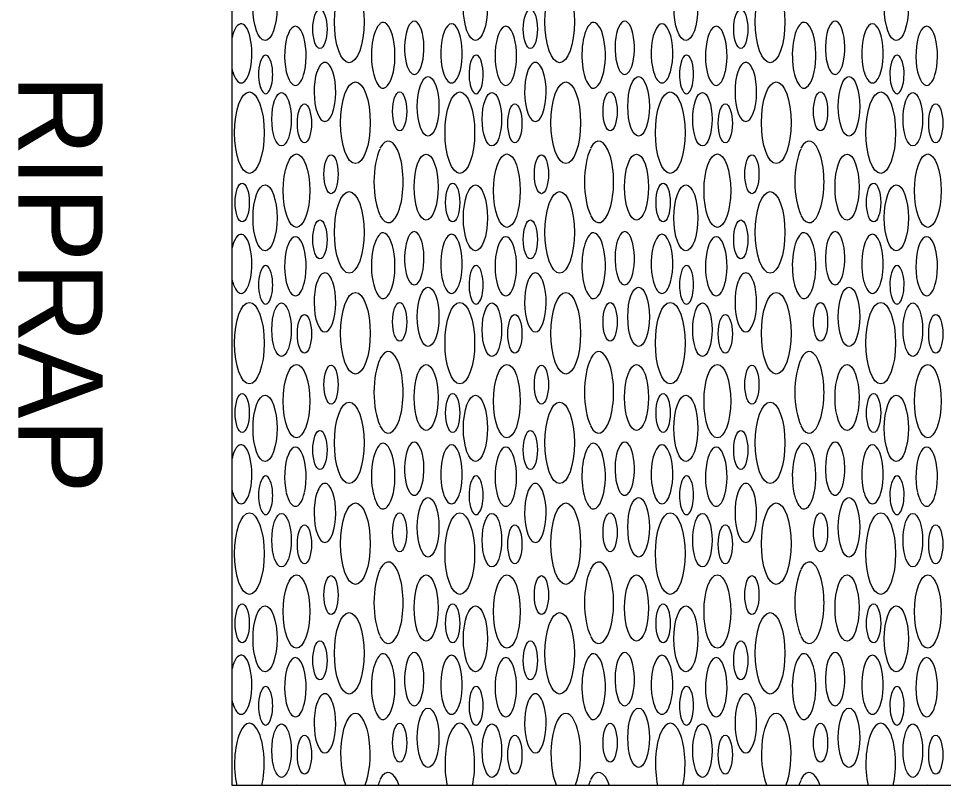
# Model space of a CAD drawing. Extents: x 2751 to 3858, y 6160 to 8366.
# Drawn here: x 3314.5 to 3534.1, y 6603.9 to 6786.1 of the extents above; entities that cross this region are included whole.
import ezdxf

# ---------------------------------------------------------------- set-up
doc = ezdxf.new("R2010")
doc.units = 0
doc.layers.add('Default', color=7, linetype='Continuous')

msp = doc.modelspace()

# ---------------------------------------------------------------- linework, layer by layer
at = {"layer": 'Default'}
msp.add_lwpolyline([(3658.73, 6840.75), (3658.73, 6603.91), (3365.15, 6603.91), (3365.15, 6840.75)], close=True, dxfattribs=at)
for centre, major_axis in [((3372.98, 6788.77), (0, 7.85)), ((3422.94, 6788.77), (0, 7.85)), ((3472.91, 6788.77), (0, 7.85)), ((3522.88, 6788.77), (0, 7.85)), ((3392.97, 6785.32), (0, 9.69)), ((3442.94, 6785.32), (0, 9.69)), ((3492.91, 6785.32), (0, 9.69)), ((3386.02, 6783.64), (0, 4.63)), ((3435.98, 6783.64), (0, 4.63)), ((3485.95, 6783.64), (0, 4.63)), ((3411.71, 6765.26), (0, 7.06)), ((3461.68, 6765.26), (0, 7.06)), ((3511.64, 6765.26), (0, 7.06)), ((3394.44, 6761.36), (0, 9.69)), ((3444.4, 6761.36), (0, 9.69)), ((3494.37, 6761.36), (0, 9.69)), ((3369.27, 6759.01), (0, 9.69)), ((3376.9, 6762.2), (0, 6.35)), ((3404.95, 6764.07), (0, 4.63)), ((3419.24, 6759.01), (0, 9.69)), ((3426.86, 6762.2), (0, 6.35)), ((3454.92, 6764.07), (0, 4.63)), ((3469.2, 6759.01), (0, 9.69)), ((3476.83, 6762.2), (0, 6.35)), ((3504.89, 6764.07), (0, 4.63)), ((3519.17, 6759.01), (0, 9.69)), ((3526.8, 6762.2), (0, 6.35)), ((3382.34, 6761.22), (0, 4.63)), ((3432.31, 6761.22), (0, 4.63)), ((3482.27, 6761.22), (0, 4.63)), ((3532.24, 6761.22), (0, 4.63)), ((3380.45, 6745.24), (0, 8.72)), ((3388.66, 6749.15), (0, 4.63)), ((3411.23, 6746.09), (0, 7.85)), ((3430.42, 6745.24), (0, 8.72)), ((3438.62, 6749.15), (0, 4.63)), ((3461.2, 6746.09), (0, 7.85)), ((3480.38, 6745.24), (0, 8.72)), ((3488.59, 6749.15), (0, 4.63)), ((3511.17, 6746.09), (0, 7.85)), ((3530.35, 6745.24), (0, 8.72)), ((3367.57, 6742.42), (0, 4.63)), ((3417.54, 6742.42), (0, 4.63)), ((3467.51, 6742.42), (0, 4.63)), ((3517.48, 6742.42), (0, 4.63)), ((3372.98, 6738.77), (0, 7.85)), ((3392.97, 6735.32), (0, 9.69)), ((3422.94, 6738.77), (0, 7.85)), ((3442.94, 6735.32), (0, 9.69)), ((3472.91, 6738.77), (0, 7.85)), ((3492.91, 6735.32), (0, 9.69)), ((3522.88, 6738.77), (0, 7.85)), ((3386.02, 6733.64), (0, 4.63)), ((3435.98, 6733.64), (0, 4.63)), ((3485.95, 6733.64), (0, 4.63)), ((3394.44, 6711.36), (0, 9.69)), ((3411.71, 6715.26), (0, 7.06)), ((3444.4, 6711.36), (0, 9.69)), ((3461.68, 6715.26), (0, 7.06)), ((3494.37, 6711.36), (0, 9.69)), ((3511.64, 6715.26), (0, 7.06)), ((3369.27, 6709.01), (0, 9.69)), ((3376.9, 6712.2), (0, 6.35)), ((3404.95, 6714.07), (0, 4.63)), ((3419.24, 6709.01), (0, 9.69)), ((3426.86, 6712.2), (0, 6.35)), ((3454.92, 6714.07), (0, 4.63)), ((3469.2, 6709.01), (0, 9.69)), ((3476.83, 6712.2), (0, 6.35)), ((3504.89, 6714.07), (0, 4.63)), ((3519.17, 6709.01), (0, 9.69)), ((3526.8, 6712.2), (0, 6.35)), ((3382.34, 6711.22), (0, 4.63)), ((3432.31, 6711.22), (0, 4.63)), ((3482.27, 6711.22), (0, 4.63)), ((3532.24, 6711.22), (0, 4.63)), ((3380.45, 6695.24), (0, 8.72)), ((3388.66, 6699.15), (0, 4.63)), ((3411.23, 6696.09), (0, 7.85)), ((3430.42, 6695.24), (0, 8.72)), ((3438.62, 6699.15), (0, 4.63)), ((3461.2, 6696.09), (0, 7.85)), ((3480.38, 6695.24), (0, 8.72)), ((3488.59, 6699.15), (0, 4.63)), ((3511.17, 6696.09), (0, 7.85)), ((3530.35, 6695.24), (0, 8.72)), ((3367.57, 6692.42), (0, 4.63)), ((3372.98, 6688.77), (0, 7.85)), ((3417.54, 6692.42), (0, 4.63)), ((3422.94, 6688.77), (0, 7.85)), ((3467.51, 6692.42), (0, 4.63)), ((3472.91, 6688.77), (0, 7.85)), ((3517.48, 6692.42), (0, 4.63)), ((3522.88, 6688.77), (0, 7.85)), ((3392.97, 6685.32), (0, 9.69)), ((3442.94, 6685.32), (0, 9.69)), ((3492.91, 6685.32), (0, 9.69)), ((3386.02, 6683.64), (0, 4.63)), ((3435.98, 6683.64), (0, 4.63)), ((3485.95, 6683.64), (0, 4.63)), ((3394.44, 6661.36), (0, 9.69)), ((3411.71, 6665.26), (0, 7.06)), ((3444.4, 6661.36), (0, 9.69)), ((3461.68, 6665.26), (0, 7.06)), ((3494.37, 6661.36), (0, 9.69)), ((3511.64, 6665.26), (0, 7.06)), ((3369.27, 6659.01), (0, 9.69)), ((3376.9, 6662.2), (0, 6.35)), ((3404.95, 6664.07), (0, 4.63)), ((3419.24, 6659.01), (0, 9.69)), ((3426.86, 6662.2), (0, 6.35)), ((3454.92, 6664.07), (0, 4.63)), ((3469.2, 6659.01), (0, 9.69)), ((3476.83, 6662.2), (0, 6.35)), ((3504.89, 6664.07), (0, 4.63)), ((3519.17, 6659.01), (0, 9.69)), ((3526.8, 6662.2), (0, 6.35)), ((3382.34, 6661.22), (0, 4.63)), ((3432.31, 6661.22), (0, 4.63)), ((3482.27, 6661.22), (0, 4.63)), ((3532.24, 6661.22), (0, 4.63)), ((3380.45, 6645.24), (0, 8.72)), ((3388.66, 6649.15), (0, 4.63)), ((3411.23, 6646.09), (0, 7.85)), ((3430.42, 6645.24), (0, 8.72)), ((3438.62, 6649.15), (0, 4.63)), ((3461.2, 6646.09), (0, 7.85)), ((3480.38, 6645.24), (0, 8.72)), ((3488.59, 6649.15), (0, 4.63)), ((3511.17, 6646.09), (0, 7.85)), ((3530.35, 6645.24), (0, 8.72)), ((3367.57, 6642.42), (0, 4.63)), ((3372.98, 6638.77), (0, 7.85)), ((3417.54, 6642.42), (0, 4.63)), ((3422.94, 6638.77), (0, 7.85)), ((3467.51, 6642.42), (0, 4.63)), ((3472.91, 6638.77), (0, 7.85)), ((3517.48, 6642.42), (0, 4.63)), ((3522.88, 6638.77), (0, 7.85)), ((3392.97, 6635.32), (0, 9.69)), ((3442.94, 6635.32), (0, 9.69)), ((3492.91, 6635.32), (0, 9.69)), ((3386.02, 6633.64), (0, 4.63)), ((3435.98, 6633.64), (0, 4.63)), ((3485.95, 6633.64), (0, 4.63)), ((3411.71, 6615.26), (0, 7.06)), ((3461.68, 6615.26), (0, 7.06)), ((3511.64, 6615.26), (0, 7.06)), ((3376.9, 6612.2), (0, 6.35)), ((3404.95, 6614.07), (0, 4.63)), ((3426.86, 6612.2), (0, 6.35)), ((3454.92, 6614.07), (0, 4.63)), ((3476.83, 6612.2), (0, 6.35)), ((3504.89, 6614.07), (0, 4.63)), ((3526.8, 6612.2), (0, 6.35)), ((3382.34, 6611.22), (0, 4.63)), ((3432.31, 6611.22), (0, 4.63)), ((3482.27, 6611.22), (0, 4.63)), ((3532.24, 6611.22), (0, 4.63))]:
    msp.add_ellipse(centre, major_axis=major_axis, ratio=0.363008, dxfattribs=at)
for centre, major_axis, start_param, end_param in [((3367.31, 6777.81), (0, 7.06), 4.052158, 7.284483), ((3380.19, 6777.23), (0, 7.06), 4.153427, 8.412944), ((3401.1, 6777.37), (0, 7.85), 0.290369, 2.088937), ((3400.99, 6777.37), (0, 7.85), 4.194248, 6.537164), ((3408.42, 6779.15), (0, 6.35), 3.611534, 8.954836), ((3417.27, 6777.81), (0, 7.06), 4.052158, 8.514212), ((3430.16, 6777.23), (0, 7.06), 4.153427, 8.412944), ((3451.07, 6777.37), (0, 7.85), 0.290369, 2.088937), ((3450.95, 6777.37), (0, 7.85), 4.194248, 6.537164), ((3458.39, 6779.15), (0, 6.35), 3.611534, 8.954836), ((3467.24, 6777.81), (0, 7.06), 4.052158, 8.514212), ((3480.12, 6777.23), (0, 7.06), 4.153427, 8.412944), ((3501.03, 6777.37), (0, 7.85), 0.290369, 2.088937), ((3500.92, 6777.37), (0, 7.85), 4.194248, 6.537164), ((3508.35, 6779.15), (0, 6.35), 3.611534, 8.954836), ((3517.21, 6777.81), (0, 7.06), 4.052158, 8.514212), ((3530.09, 6777.23), (0, 7.06), 4.153427, 8.412944), ((3373.13, 6772.83), (0, 4.63), 4.854561, 7.711809), ((3387.2, 6768.64), (0, 7.06), 5.46767, 7.0987), ((3423.1, 6772.83), (0, 4.63), 4.854561, 7.711809), ((3437.17, 6768.64), (0, 7.06), 5.46767, 7.0987), ((3473.07, 6772.83), (0, 4.63), 4.854561, 7.711809), ((3487.14, 6768.64), (0, 7.06), 5.46767, 7.0987), ((3523.04, 6772.83), (0, 4.63), 4.854561, 7.711809), ((3367.31, 6777.81), (0, 7.06), 2.140295, 2.231027), ((3367.31, 6777.89), (0, 7.06), 2.24426, 4.038925), ((3373.13, 6772.9), (0, 4.63), 1.444874, 4.838315), ((3380.19, 6777.3), (0, 7.06), 2.142081, 4.141105), ((3387.2, 6768.72), (0, 7.06), 0.8307, 5.452486), ((3401.1, 6777.44), (0, 7.85), 2.099726, 2.851228), ((3400.99, 6777.44), (0, 7.85), 2.887614, 4.183498), ((3408.42, 6779.22), (0, 6.35), 2.698408, 3.585582), ((3417.27, 6777.89), (0, 7.06), 2.24426, 4.038925), ((3423.1, 6772.9), (0, 4.63), 1.444874, 4.838315), ((3430.16, 6777.3), (0, 7.06), 2.142081, 4.141105), ((3437.17, 6768.72), (0, 7.06), 0.8307, 5.452486), ((3451.07, 6777.44), (0, 7.85), 2.099726, 2.851228), ((3450.95, 6777.44), (0, 7.85), 2.887614, 4.183498), ((3458.39, 6779.22), (0, 6.35), 2.698408, 3.585582), ((3467.24, 6777.89), (0, 7.06), 2.24426, 4.038925), ((3473.07, 6772.9), (0, 4.63), 1.444874, 4.838315), ((3480.12, 6777.3), (0, 7.06), 2.142081, 4.141105), ((3487.14, 6768.72), (0, 7.06), 0.8307, 5.452486), ((3501.03, 6777.44), (0, 7.85), 2.099726, 2.851228), ((3500.92, 6777.44), (0, 7.85), 2.887614, 4.183498), ((3508.35, 6779.22), (0, 6.35), 2.698408, 3.585582), ((3517.21, 6777.89), (0, 7.06), 2.24426, 4.038925), ((3523.04, 6772.9), (0, 4.63), 1.444874, 4.838315), ((3530.09, 6777.3), (0, 7.06), 2.142081, 4.141105), ((3402.26, 6747.32), (0, 9.69), 2.54052, 6.884258), ((3452.23, 6747.32), (0, 9.69), 2.54052, 6.884258), ((3502.19, 6747.32), (0, 9.69), 2.54052, 6.884258), ((3402.37, 6747.32), (0, 9.69), 0.635873, 2.505716), ((3452.34, 6747.32), (0, 9.69), 0.635873, 2.505716), ((3502.31, 6747.32), (0, 9.69), 0.635873, 2.505716), ((3367.31, 6727.81), (0, 7.06), 4.052158, 7.284483), ((3380.19, 6727.23), (0, 7.06), 4.153427, 8.412944), ((3401.1, 6727.37), (0, 7.85), 0.290369, 2.088937), ((3400.99, 6727.37), (0, 7.85), 4.194248, 6.537164), ((3408.42, 6729.15), (0, 6.35), 3.611534, 8.954836), ((3417.27, 6727.81), (0, 7.06), 4.052158, 8.514212), ((3430.16, 6727.23), (0, 7.06), 4.153427, 8.412944), ((3451.07, 6727.37), (0, 7.85), 0.290369, 2.088937), ((3450.95, 6727.37), (0, 7.85), 4.194248, 6.537164), ((3458.39, 6729.15), (0, 6.35), 3.611534, 8.954836), ((3467.24, 6727.81), (0, 7.06), 4.052158, 8.514212), ((3480.12, 6727.23), (0, 7.06), 4.153427, 8.412944), ((3501.03, 6727.37), (0, 7.85), 0.290369, 2.088937), ((3500.92, 6727.37), (0, 7.85), 4.194248, 6.537164), ((3508.35, 6729.15), (0, 6.35), 3.611534, 8.954836), ((3517.21, 6727.81), (0, 7.06), 4.052158, 8.514212), ((3530.09, 6727.23), (0, 7.06), 4.153427, 8.412944), ((3373.13, 6722.83), (0, 4.63), 4.854561, 7.711809), ((3423.1, 6722.83), (0, 4.63), 4.854561, 7.711809), ((3473.07, 6722.83), (0, 4.63), 4.854561, 7.711809), ((3523.04, 6722.83), (0, 4.63), 4.854561, 7.711809), ((3387.2, 6718.64), (0, 7.06), 5.46767, 7.0987), ((3437.17, 6718.64), (0, 7.06), 5.46767, 7.0987), ((3487.14, 6718.64), (0, 7.06), 5.46767, 7.0987), ((3367.31, 6727.81), (0, 7.06), 2.140295, 2.231027), ((3367.31, 6727.89), (0, 7.06), 2.24426, 4.038925), ((3373.13, 6722.9), (0, 4.63), 1.444874, 4.838315), ((3380.19, 6727.3), (0, 7.06), 2.142081, 4.141105), ((3387.2, 6718.72), (0, 7.06), 0.8307, 5.452486), ((3401.1, 6727.44), (0, 7.85), 2.099726, 2.851228), ((3400.99, 6727.44), (0, 7.85), 2.887614, 4.183498), ((3408.42, 6729.22), (0, 6.35), 2.698408, 3.585582), ((3417.27, 6727.89), (0, 7.06), 2.24426, 4.038925), ((3423.1, 6722.9), (0, 4.63), 1.444874, 4.838315), ((3430.16, 6727.3), (0, 7.06), 2.142081, 4.141105), ((3437.17, 6718.72), (0, 7.06), 0.8307, 5.452486), ((3451.07, 6727.44), (0, 7.85), 2.099726, 2.851228), ((3450.95, 6727.44), (0, 7.85), 2.887614, 4.183498), ((3458.39, 6729.22), (0, 6.35), 2.698408, 3.585582), ((3467.24, 6727.89), (0, 7.06), 2.24426, 4.038925), ((3473.07, 6722.9), (0, 4.63), 1.444874, 4.838315), ((3480.12, 6727.3), (0, 7.06), 2.142081, 4.141105), ((3487.14, 6718.72), (0, 7.06), 0.8307, 5.452486), ((3501.03, 6727.44), (0, 7.85), 2.099726, 2.851228), ((3500.92, 6727.44), (0, 7.85), 2.887614, 4.183498), ((3508.35, 6729.22), (0, 6.35), 2.698408, 3.585582), ((3517.21, 6727.89), (0, 7.06), 2.24426, 4.038925), ((3523.04, 6722.9), (0, 4.63), 1.444874, 4.838315), ((3530.09, 6727.3), (0, 7.06), 2.142081, 4.141105), ((3402.26, 6697.32), (0, 9.69), 2.54052, 6.884258), ((3452.23, 6697.32), (0, 9.69), 2.54052, 6.884258), ((3502.19, 6697.32), (0, 9.69), 2.54052, 6.884258), ((3402.37, 6697.32), (0, 9.69), 0.635873, 2.505716), ((3452.34, 6697.32), (0, 9.69), 0.635873, 2.505716), ((3502.31, 6697.32), (0, 9.69), 0.635873, 2.505716), ((3400.99, 6677.37), (0, 7.85), 4.194248, 6.537164), ((3450.95, 6677.37), (0, 7.85), 4.194248, 6.537164), ((3500.92, 6677.37), (0, 7.85), 4.194248, 6.537164), ((3367.31, 6677.81), (0, 7.06), 4.052158, 7.284483), ((3380.19, 6677.23), (0, 7.06), 4.153427, 8.412944), ((3401.1, 6677.37), (0, 7.85), 0.290369, 2.088937), ((3408.42, 6679.15), (0, 6.35), 3.611534, 8.954836), ((3417.27, 6677.81), (0, 7.06), 4.052158, 8.514212), ((3430.16, 6677.23), (0, 7.06), 4.153427, 8.412944), ((3451.07, 6677.37), (0, 7.85), 0.290369, 2.088937), ((3458.39, 6679.15), (0, 6.35), 3.611534, 8.954836), ((3467.24, 6677.81), (0, 7.06), 4.052158, 8.514212), ((3480.12, 6677.23), (0, 7.06), 4.153427, 8.412944), ((3501.03, 6677.37), (0, 7.85), 0.290369, 2.088937), ((3508.35, 6679.15), (0, 6.35), 3.611534, 8.954836), ((3517.21, 6677.81), (0, 7.06), 4.052158, 8.514212), ((3530.09, 6677.23), (0, 7.06), 4.153427, 8.412944), ((3373.13, 6672.83), (0, 4.63), 4.854561, 7.711809), ((3423.1, 6672.83), (0, 4.63), 4.854561, 7.711809), ((3473.07, 6672.83), (0, 4.63), 4.854561, 7.711809), ((3523.04, 6672.83), (0, 4.63), 4.854561, 7.711809), ((3387.2, 6668.64), (0, 7.06), 5.46767, 7.0987), ((3437.17, 6668.64), (0, 7.06), 5.46767, 7.0987), ((3487.14, 6668.64), (0, 7.06), 5.46767, 7.0987), ((3367.31, 6677.81), (0, 7.06), 2.140295, 2.231027), ((3367.31, 6677.89), (0, 7.06), 2.24426, 4.038925), ((3373.13, 6672.9), (0, 4.63), 1.444874, 4.838315), ((3380.19, 6677.3), (0, 7.06), 2.142081, 4.141105), ((3387.2, 6668.72), (0, 7.06), 0.8307, 5.452486), ((3401.1, 6677.44), (0, 7.85), 2.099726, 2.851228), ((3400.99, 6677.44), (0, 7.85), 2.887614, 4.183498), ((3408.42, 6679.22), (0, 6.35), 2.698408, 3.585582), ((3417.27, 6677.89), (0, 7.06), 2.24426, 4.038925), ((3423.1, 6672.9), (0, 4.63), 1.444874, 4.838315), ((3430.16, 6677.3), (0, 7.06), 2.142081, 4.141105), ((3437.17, 6668.72), (0, 7.06), 0.8307, 5.452486), ((3451.07, 6677.44), (0, 7.85), 2.099726, 2.851228), ((3450.95, 6677.44), (0, 7.85), 2.887614, 4.183498), ((3458.39, 6679.22), (0, 6.35), 2.698408, 3.585582), ((3467.24, 6677.89), (0, 7.06), 2.24426, 4.038925), ((3473.07, 6672.9), (0, 4.63), 1.444874, 4.838315), ((3480.12, 6677.3), (0, 7.06), 2.142081, 4.141105), ((3487.14, 6668.72), (0, 7.06), 0.8307, 5.452486), ((3501.03, 6677.44), (0, 7.85), 2.099726, 2.851228), ((3500.92, 6677.44), (0, 7.85), 2.887614, 4.183498), ((3508.35, 6679.22), (0, 6.35), 2.698408, 3.585582), ((3517.21, 6677.89), (0, 7.06), 2.24426, 4.038925), ((3523.04, 6672.9), (0, 4.63), 1.444874, 4.838315), ((3530.09, 6677.3), (0, 7.06), 2.142081, 4.141105), ((3402.26, 6647.32), (0, 9.69), 2.54052, 6.884258), ((3452.23, 6647.32), (0, 9.69), 2.54052, 6.884258), ((3502.19, 6647.32), (0, 9.69), 2.54052, 6.884258), ((3402.37, 6647.32), (0, 9.69), 0.635873, 2.505716), ((3452.34, 6647.32), (0, 9.69), 0.635873, 2.505716), ((3502.31, 6647.32), (0, 9.69), 0.635873, 2.505716), ((3367.31, 6627.81), (0, 7.06), 4.052158, 7.284483), ((3400.99, 6627.37), (0, 7.85), 4.194248, 6.537164), ((3408.42, 6629.15), (0, 6.35), 3.611534, 8.954836), ((3417.27, 6627.81), (0, 7.06), 4.052158, 8.514212), ((3450.95, 6627.37), (0, 7.85), 4.194248, 6.537164), ((3458.39, 6629.15), (0, 6.35), 3.611534, 8.954836), ((3467.24, 6627.81), (0, 7.06), 4.052158, 8.514212), ((3500.92, 6627.37), (0, 7.85), 4.194248, 6.537164), ((3508.35, 6629.15), (0, 6.35), 3.611534, 8.954836), ((3517.21, 6627.81), (0, 7.06), 4.052158, 8.514212), ((3380.19, 6627.23), (0, 7.06), 4.153427, 8.412944), ((3401.1, 6627.37), (0, 7.85), 0.290369, 2.088937), ((3430.16, 6627.23), (0, 7.06), 4.153427, 8.412944), ((3451.07, 6627.37), (0, 7.85), 0.290369, 2.088937), ((3480.12, 6627.23), (0, 7.06), 4.153427, 8.412944), ((3501.03, 6627.37), (0, 7.85), 0.290369, 2.088937), ((3530.09, 6627.23), (0, 7.06), 4.153427, 8.412944), ((3373.13, 6622.83), (0, 4.63), 4.854561, 7.711809), ((3423.1, 6622.83), (0, 4.63), 4.854561, 7.711809), ((3473.07, 6622.83), (0, 4.63), 4.854561, 7.711809), ((3523.04, 6622.83), (0, 4.63), 4.854561, 7.711809), ((3387.2, 6618.64), (0, 7.06), 5.46767, 7.0987), ((3437.17, 6618.64), (0, 7.06), 5.46767, 7.0987), ((3487.14, 6618.64), (0, 7.06), 5.46767, 7.0987), ((3367.31, 6627.81), (0, 7.06), 2.140295, 2.231027), ((3367.31, 6627.89), (0, 7.06), 2.24426, 4.038925), ((3373.13, 6622.9), (0, 4.63), 1.444874, 4.838315), ((3380.19, 6627.3), (0, 7.06), 2.142081, 4.141105), ((3387.2, 6618.72), (0, 7.06), 0.8307, 5.452486), ((3401.1, 6627.44), (0, 7.85), 2.099726, 2.851228), ((3400.99, 6627.44), (0, 7.85), 2.887614, 4.183498), ((3408.42, 6629.22), (0, 6.35), 2.698408, 3.585582), ((3417.27, 6627.89), (0, 7.06), 2.24426, 4.038925), ((3423.1, 6622.9), (0, 4.63), 1.444874, 4.838315), ((3430.16, 6627.3), (0, 7.06), 2.142081, 4.141105), ((3437.17, 6618.72), (0, 7.06), 0.8307, 5.452486), ((3451.07, 6627.44), (0, 7.85), 2.099726, 2.851228), ((3450.95, 6627.44), (0, 7.85), 2.887614, 4.183498), ((3458.39, 6629.22), (0, 6.35), 2.698408, 3.585582), ((3467.24, 6627.89), (0, 7.06), 2.24426, 4.038925), ((3473.07, 6622.9), (0, 4.63), 1.444874, 4.838315), ((3480.12, 6627.3), (0, 7.06), 2.142081, 4.141105), ((3487.14, 6618.72), (0, 7.06), 0.8307, 5.452486), ((3501.03, 6627.44), (0, 7.85), 2.099726, 2.851228), ((3500.92, 6627.44), (0, 7.85), 2.887614, 4.183498), ((3508.35, 6629.22), (0, 6.35), 2.698408, 3.585582), ((3517.21, 6627.89), (0, 7.06), 2.24426, 4.038925), ((3523.04, 6622.9), (0, 4.63), 1.444874, 4.838315), ((3530.09, 6627.3), (0, 7.06), 2.142081, 4.141105), ((3394.44, 6611.36), (0, 9.69), 3.834952, 8.731419), ((3444.4, 6611.36), (0, 9.69), 3.834952, 8.731419), ((3494.37, 6611.36), (0, 9.69), 3.834952, 8.731419), ((3369.27, 6609.01), (0, 9.69), 4.157815, 8.408555), ((3419.24, 6609.01), (0, 9.69), 4.157815, 8.408555), ((3469.2, 6609.01), (0, 9.69), 4.157815, 8.408555), ((3519.17, 6609.01), (0, 9.69), 4.157815, 8.408555), ((3402.26, 6597.32), (0, 9.69), 5.461325, 6.884258), ((3452.23, 6597.32), (0, 9.69), 5.461325, 6.884258), ((3502.19, 6597.32), (0, 9.69), 5.461325, 6.884258), ((3402.37, 6597.32), (0, 9.69), 0.635873, 0.82186), ((3452.34, 6597.32), (0, 9.69), 0.635873, 0.82186), ((3502.31, 6597.32), (0, 9.69), 0.635873, 0.82186), ((3380.45, 6595.24), (0, 8.72), 6.182114, 6.384257), ((3411.23, 6596.09), (0, 7.85), 6.207145, 6.359225), ((3430.42, 6595.24), (0, 8.72), 6.182114, 6.384257), ((3461.2, 6596.09), (0, 7.85), 6.207145, 6.359225), ((3480.38, 6595.24), (0, 8.72), 6.182114, 6.384257), ((3511.17, 6596.09), (0, 7.85), 6.207145, 6.359225), ((3530.35, 6595.24), (0, 8.72), 6.182114, 6.384257)]:
    msp.add_ellipse(centre, major_axis=major_axis, ratio=0.363008, start_param=start_param, end_param=end_param, dxfattribs=at)

# ---------------------------------------------------------------- texts
msp.add_text('RIPRAP', height=20, rotation=270, dxfattribs=at).set_placement((3314.45, 6772.88))

doc.saveas('drawing.dxf')
